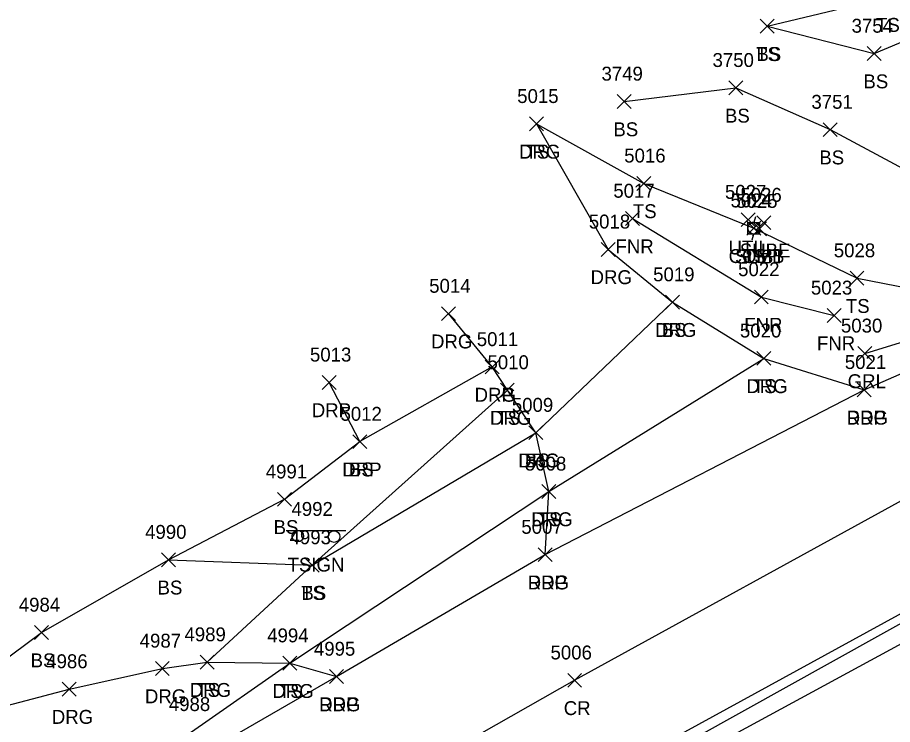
# Model space of a CAD drawing. Extents: x 1505656 to 1508446, y 700805 to 703031.
# Drawn here: x 1506226.3 to 1506352.2, y 701708.7 to 701810.4 of the extents above; entities that cross this region are included whole.
import ezdxf

# ---------------------------------------------------------------- set-up
doc = ezdxf.new("R2010")
doc.units = 0
for name, color, linetype in [('L_A', 7, 'Continuous'), ('L_I', 7, 'Continuous'), ('L_TIC', 7, 'Continuous'), ('LASF', 7, 'Continuous'), ('LELB', 7, 'Continuous'), ('LFNC', 7, 'Continuous'), ('P_A', 7, 'Continuous'), ('P_I', 7, 'Continuous'), ('P_TIC', 7, 'Continuous'), ('PET', 7, 'Continuous'), ('PRC', 7, 'Continuous'), ('R_A', 7, 'Continuous'), ('R_I', 7, 'Continuous'), ('R_TIC', 7, 'Continuous'), ('RDG', 7, 'Continuous'), ('RDP', 7, 'Continuous'), ('RGR', 7, 'Continuous'), ('S_A', 7, 'Continuous'), ('S_I', 7, 'Continuous'), ('SSGN', 7, 'Continuous'), ('U_A', 7, 'Continuous'), ('U_I', 7, 'Continuous'), ('U_TIC', 7, 'Continuous'), ('UDEFAULT', 7, 'Continuous'), ('UP', 7, 'Continuous')]:
    doc.layers.add(name, color=color, linetype=linetype)

msp = doc.modelspace()

# ---------------------------------------------------------------- linework, layer by layer
at = {"layer": 'L_TIC'}
for points in [[(1506333.15, 701808.13), (1506335.15, 701810.13)], [(1506335.15, 701808.13), (1506333.15, 701810.13)], [(1506333.15, 701808.13), (1506335.15, 701810.13)], [(1506335.15, 701808.13), (1506333.15, 701810.13)], [(1506348.54, 701804.2), (1506350.54, 701806.2)], [(1506350.54, 701804.2), (1506348.54, 701806.2)], [(1506328.63, 701799.27), (1506330.63, 701801.27)], [(1506330.63, 701799.27), (1506328.63, 701801.27)], [(1506312.58, 701797.31), (1506314.58, 701799.31)], [(1506314.58, 701797.31), (1506312.58, 701799.31)], [(1506299.96, 701794.09), (1506301.96, 701796.09)], [(1506301.96, 701794.09), (1506299.96, 701796.09)], [(1506342.19, 701793.26), (1506344.19, 701795.26)], [(1506344.19, 701793.26), (1506342.19, 701795.26)], [(1506315.41, 701785.53), (1506317.41, 701787.53)], [(1506317.41, 701785.53), (1506315.41, 701787.53)], [(1506313.78, 701780.47), (1506315.78, 701782.47)], [(1506315.78, 701780.47), (1506313.78, 701782.47)], [(1506331.21, 701779.08), (1506333.21, 701781.08)], [(1506333.21, 701779.08), (1506331.21, 701781.08)], [(1506346.06, 701771.9), (1506348.06, 701773.9)], [(1506348.06, 701771.9), (1506346.06, 701773.9)], [(1506319.52, 701768.45), (1506321.52, 701770.45)], [(1506321.52, 701768.45), (1506319.52, 701770.45)], [(1506332.3, 701769.19), (1506334.3, 701771.19)], [(1506334.3, 701769.19), (1506332.3, 701771.19)], [(1506342.77, 701766.54), (1506344.77, 701768.54)], [(1506344.77, 701766.54), (1506342.77, 701768.54)], [(1506332.65, 701760.37), (1506334.65, 701762.37)], [(1506334.65, 701760.37), (1506332.65, 701762.37)], [(1506295.77, 701755.81), (1506297.77, 701757.81)], [(1506297.77, 701755.81), (1506295.77, 701757.81)], [(1506299.85, 701749.68), (1506301.85, 701751.68)], [(1506301.85, 701749.68), (1506299.85, 701751.68)], [(1506274.54, 701748.39), (1506276.54, 701750.39)], [(1506276.54, 701748.39), (1506274.54, 701750.39)], [(1506301.72, 701741.23), (1506303.72, 701743.23)], [(1506303.72, 701741.23), (1506301.72, 701743.23)], [(1506263.71, 701740.1), (1506265.71, 701742.1)], [(1506265.71, 701740.1), (1506263.71, 701742.1)], [(1506247.02, 701731.41), (1506249.02, 701733.41)], [(1506249.02, 701731.41), (1506247.02, 701733.41)], [(1506247.02, 701731.41), (1506249.02, 701733.41)], [(1506249.02, 701731.41), (1506247.02, 701733.41)], [(1506267.71, 701730.64), (1506269.71, 701732.64)], [(1506269.71, 701730.64), (1506267.71, 701732.64)], [(1506267.71, 701730.64), (1506269.71, 701732.64)], [(1506269.71, 701730.64), (1506267.71, 701732.64)], [(1506228.76, 701720.94), (1506230.76, 701722.94)], [(1506230.76, 701720.94), (1506228.76, 701722.94)], [(1506252.6, 701716.68), (1506254.6, 701718.68)], [(1506254.6, 701716.68), (1506252.6, 701718.68)], [(1506264.49, 701716.53), (1506266.49, 701718.53)], [(1506266.49, 701716.53), (1506264.49, 701718.53)]]:
    msp.add_lwpolyline(points, dxfattribs=at)
at = {"layer": 'LASF'}
msp.add_lwpolyline([(1506429.68, 701752.83), (1506443.79, 701749.58), (1506462.7, 701738.25), (1506448, 701734.79), (1506439.12, 701730.66), (1506414.7, 701723.7), (1506383.01, 701711.36), (1506356.51, 701697.3), (1506322.23, 701673.42), (1506294.03, 701680.48), (1506288.73, 701684.49), (1506312.05, 701697.87), (1506364.79, 701726.48), (1506396.56, 701742.51), (1506417.45, 701749.86)], dxfattribs=at)
at = {"layer": 'LELB'}
for points in [[(1506334.15, 701809.13), (1506349.54, 701805.2), (1506366.68, 701812.39), (1506381.99, 701819.88), (1506387.6, 701843.4)], [(1506334.15, 701809.13), (1506351.39, 701813.32), (1506364.07, 701815.2), (1506375.49, 701824.29), (1506380.43, 701837.23)], [(1506313.58, 701798.31), (1506329.63, 701800.27), (1506343.19, 701794.26), (1506361, 701784.72), (1506379.68, 701792.88), (1506403.16, 701804.05), (1506415.96, 701807.45), (1506430.34, 701803.3), (1506438.86, 701796.52), (1506455.96, 701772), (1506464.53, 701767.06), (1506468.29, 701757.43), (1506462.7, 701738.25), (1506453.06, 701729.73), (1506439.12, 701730.66)], [(1506300.96, 701795.09), (1506316.41, 701786.53), (1506332.21, 701780.08), (1506347.06, 701772.9), (1506358.64, 701770.66), (1506379.38, 701774.98), (1506399.48, 701783.43), (1506418.59, 701789.11)], [(1506184.83, 701679.05), (1506205.21, 701698.56), (1506210.57, 701707.7), (1506229.76, 701721.94), (1506248.02, 701732.41), (1506268.71, 701731.64), (1506300.85, 701750.68), (1506320.52, 701769.45)], [(1506172.04, 701663.28), (1506192.25, 701675.22), (1506214.19, 701688.79), (1506251.34, 701707.65), (1506265.49, 701717.53), (1506302.72, 701742.23), (1506333.65, 701761.37)], [(1506253.6, 701717.68), (1506268.71, 701731.64), (1506296.77, 701756.81)], [(1506248.02, 701732.41), (1506264.71, 701741.1), (1506275.54, 701749.39)]]:
    msp.add_lwpolyline(points, dxfattribs=at)
at = {"layer": 'LFNC'}
msp.add_lwpolyline([(1506314.78, 701781.47), (1506333.3, 701770.19), (1506343.77, 701767.54)], dxfattribs=at)
at = {"layer": 'P_TIC'}
for points in [[(1506347.09, 701755.84), (1506349.09, 701757.84)], [(1506349.09, 701755.84), (1506347.09, 701757.84)], [(1506301.2, 701732.14), (1506303.2, 701734.14)], [(1506303.2, 701732.14), (1506301.2, 701734.14)], [(1506271.21, 701714.61), (1506273.21, 701716.61)], [(1506273.21, 701714.61), (1506271.21, 701716.61)], [(1506305.45, 701714.07), (1506307.45, 701716.07)], [(1506307.45, 701714.07), (1506305.45, 701716.07)]]:
    msp.add_lwpolyline(points, dxfattribs=at)
at = {"layer": 'PET'}
for points in [[(1505981.01, 701553.68), (1506020.04, 701573.54), (1506047.43, 701586.84), (1506064.36, 701596.59), (1506091.54, 701613.44), (1506142.35, 701641.39), (1506170.77, 701656.92), (1506194.97, 701672.06), (1506198.42, 701673.57), (1506217.27, 701683.91), (1506272.21, 701715.61), (1506302.2, 701733.14), (1506348.09, 701756.84), (1506381.24, 701771.36), (1506401.82, 701779.86), (1506418.98, 701787.96), (1506419.65, 701788)], [(1505992.82, 701526.62), (1506019.68, 701536.96), (1506041.12, 701547.38), (1506078.94, 701568.61), (1506107.14, 701585.72), (1506155.42, 701613.4), (1506197.61, 701637.13), (1506235.98, 701659.24), (1506270.79, 701679.06), (1506309.7, 701700.77), (1506363.1, 701730.01), (1506394.98, 701746.14), (1506415.62, 701755.89), (1506435.04, 701763.8), (1506427.31, 701775.57), (1506419.65, 701788)]]:
    msp.add_lwpolyline(points, dxfattribs=at)
at = {"layer": 'PRC'}
msp.add_lwpolyline([(1505987, 701541.07), (1506027.82, 701560.7), (1506054.36, 701574.52), (1506099.99, 701598.76), (1506149.98, 701626.58), (1506191.41, 701650.15), (1506228.11, 701670.57), (1506265.76, 701691.98), (1506306.45, 701715.07), (1506355.45, 701742.05), (1506388.92, 701758.93), (1506408.16, 701767.63), (1506427.31, 701775.57)], dxfattribs=at)
at = {"layer": 'R_TIC'}
for points in [[(1506299.96, 701794.09), (1506301.96, 701796.09)], [(1506301.96, 701794.09), (1506299.96, 701796.09)], [(1506310.26, 701776.04), (1506312.26, 701778.04)], [(1506312.26, 701776.04), (1506310.26, 701778.04)], [(1506319.52, 701768.45), (1506321.52, 701770.45)], [(1506321.52, 701768.45), (1506319.52, 701770.45)], [(1506287.3, 701766.8), (1506289.3, 701768.8)], [(1506289.3, 701766.8), (1506287.3, 701768.8)], [(1506347.17, 701761.08), (1506349.17, 701763.08)], [(1506349.17, 701761.08), (1506347.17, 701763.08)], [(1506332.65, 701760.37), (1506334.65, 701762.37)], [(1506334.65, 701760.37), (1506332.65, 701762.37)], [(1506293.57, 701759.13), (1506295.57, 701761.13)], [(1506295.57, 701759.13), (1506293.57, 701761.13)], [(1506293.57, 701759.13), (1506295.57, 701761.13)], [(1506295.57, 701759.13), (1506293.57, 701761.13)], [(1506270.15, 701756.91), (1506272.15, 701758.91)], [(1506272.15, 701756.91), (1506270.15, 701758.91)], [(1506295.77, 701755.81), (1506297.77, 701757.81)], [(1506297.77, 701755.81), (1506295.77, 701757.81)], [(1506347.09, 701755.84), (1506349.09, 701757.84)], [(1506349.09, 701755.84), (1506347.09, 701757.84)], [(1506299.85, 701749.68), (1506301.85, 701751.68)], [(1506301.85, 701749.68), (1506299.85, 701751.68)], [(1506274.54, 701748.39), (1506276.54, 701750.39)], [(1506276.54, 701748.39), (1506274.54, 701750.39)], [(1506301.72, 701741.23), (1506303.72, 701743.23)], [(1506303.72, 701741.23), (1506301.72, 701743.23)], [(1506301.2, 701732.14), (1506303.2, 701734.14)], [(1506303.2, 701732.14), (1506301.2, 701734.14)], [(1506252.6, 701716.68), (1506254.6, 701718.68)], [(1506254.6, 701716.68), (1506252.6, 701718.68)], [(1506264.49, 701716.53), (1506266.49, 701718.53)], [(1506266.49, 701716.53), (1506264.49, 701718.53)], [(1506246.15, 701715.77), (1506248.15, 701717.77)], [(1506248.15, 701715.77), (1506246.15, 701717.77)], [(1506271.21, 701714.61), (1506273.21, 701716.61)], [(1506273.21, 701714.61), (1506271.21, 701716.61)], [(1506232.76, 701712.81), (1506234.76, 701714.81)], [(1506234.76, 701712.81), (1506232.76, 701714.81)]]:
    msp.add_lwpolyline(points, dxfattribs=at)
at = {"layer": 'RDG'}
for points in [[(1506300.96, 701795.09), (1506311.26, 701777.04), (1506320.52, 701769.45), (1506333.65, 701761.37), (1506348.09, 701756.84)], [(1506302.2, 701733.14), (1506302.72, 701742.23), (1506300.85, 701750.68), (1506296.77, 701756.81), (1506294.57, 701760.13), (1506288.3, 701767.8)], [(1506199.34, 701711.36), (1506210.57, 701707.7), (1506233.76, 701713.81), (1506247.15, 701716.77), (1506253.6, 701717.68), (1506265.49, 701717.53), (1506272.21, 701715.61)]]:
    msp.add_lwpolyline(points, dxfattribs=at)
at = {"layer": 'RDP'}
msp.add_lwpolyline([(1506294.57, 701760.13), (1506275.54, 701749.39), (1506271.15, 701757.91)], dxfattribs=at)
at = {"layer": 'RGR'}
for points in [[(1506348.17, 701762.08), (1506380.89, 701772.12), (1506400.77, 701781.19), (1506418.59, 701789.11)], [(1506085.73, 701568.29), (1506107.54, 701584.72), (1506155.8, 701612.35), (1506198.2, 701636.56), (1506236.66, 701658.36), (1506270.99, 701677.92), (1506310.51, 701699.4), (1506363.66, 701728.98), (1506395.74, 701744.99), (1506415.68, 701754.26), (1506427.01, 701758.86)]]:
    msp.add_lwpolyline(points, dxfattribs=at)
at = {"layer": 'SSGN'}
for p, q in [((1506264.97, 701736.63), (1506273.56, 701736.63)), ((1506268.99, 701735.73), (1506268.99, 701735.73))]:
    msp.add_line(p, q, dxfattribs=at)
for centre in [(1506266.63, 701735.8), (1506271.84, 701735.73)]:
    msp.add_circle(centre, 0.833, dxfattribs=at)
at = {"layer": 'U_TIC'}
for points in [[(1506332.67, 701779.88), (1506334.67, 701781.88)], [(1506334.67, 701779.88), (1506332.67, 701781.88)], [(1506332.02, 701779.01), (1506334.02, 701781.01)], [(1506334.02, 701779.01), (1506332.02, 701781.01)]]:
    msp.add_lwpolyline(points, dxfattribs=at)
at = {"layer": 'UDEFAULT'}
for points in [[(1506330.41, 701780.31), (1506332.41, 701782.31)], [(1506332.41, 701780.31), (1506330.41, 701782.31)]]:
    msp.add_lwpolyline(points, dxfattribs=at)
at = {"layer": 'UP'}
for p, q in [((1506332.46, 701781.74), (1506332.21, 701780.91)), ((1506331.37, 701779.24), (1506331.37, 701780.91)), ((1506331.37, 701780.91), (1506333.04, 701780.91)), ((1506332.21, 701780.08), (1506332.21, 701780.08)), ((1506333.04, 701780.91), (1506333.04, 701779.24)), ((1506333.04, 701779.24), (1506331.37, 701779.24)), ((1506331.96, 701778.41), (1506332.21, 701779.24))]:
    msp.add_line(p, q, dxfattribs=at)
msp.add_circle((1506332.21, 701780.08), 0.833, dxfattribs=at)

# ---------------------------------------------------------------- texts
at = {"layer": 'L_A'}
for s, p in [('TS', (1506349.8, 701808.32)), ('TS', (1506332.56, 701804.13)), ('BS', (1506332.59, 701804.13)), ('BS', (1506347.98, 701800.2)), ('BS', (1506328.07, 701795.27)), ('BS', (1506312.02, 701793.31)), ('TS', (1506299.37, 701790.09)), ('BS', (1506341.64, 701789.26)), ('TS', (1506314.82, 701781.53)), ('FNR', (1506312.32, 701776.47)), ('TS', (1506330.62, 701775.08)), ('TS', (1506345.46, 701767.9)), ('BS', (1506318.96, 701764.45)), ('FNR', (1506330.84, 701765.19)), ('FNR', (1506341.3, 701762.54)), ('TS', (1506332.06, 701756.37)), ('TS', (1506295.18, 701751.81)), ('BS', (1506299.29, 701745.68)), ('BS', (1506273.98, 701744.39)), ('TS', (1506301.13, 701737.23)), ('BS', (1506263.15, 701736.1)), ('BS', (1506246.46, 701727.41)), ('BS', (1506246.46, 701727.41)), ('TS', (1506267.12, 701726.64)), ('BS', (1506267.15, 701726.64)), ('BS', (1506228.2, 701716.94)), ('TS', (1506252.01, 701712.68)), ('TS', (1506263.9, 701712.53))]:
    msp.add_text(s, height=2, dxfattribs=at).set_placement(p)
at = {"layer": 'L_I'}
for s, p in [('3754', (1506346.28, 701808.2)), ('3750', (1506326.28, 701803.27)), ('3749', (1506310.31, 701801.31)), ('5015', (1506298.19, 701798.09)), ('3751', (1506340.5, 701797.26)), ('5016', (1506313.58, 701789.53)), ('5017', (1506312.01, 701784.47)), ('5024', (1506328.87, 701783.08)), ('5028', (1506343.72, 701775.9)), ('5022', (1506329.96, 701773.19)), ('5019', (1506317.74, 701772.45)), ('5023', (1506340.43, 701770.54)), ('5020', (1506330.22, 701764.37)), ('5010', (1506293.91, 701759.81)), ('5009', (1506297.42, 701753.68)), ('5012', (1506272.77, 701752.39)), ('4991', (1506262.02, 701744.1)), ('5008', (1506299.3, 701745.23)), ('4990', (1506244.67, 701735.41)), ('4990', (1506244.67, 701735.41)), ('4993', (1506265.45, 701734.64)), ('4993', (1506265.45, 701734.64)), ('4984', (1506226.5, 701724.94)), ('4989', (1506250.33, 701720.68)), ('4994', (1506262.23, 701720.53)), ('4988', (1506248.08, 701710.65))]:
    msp.add_text(s, height=2, dxfattribs=at).set_placement(p)
at = {"layer": 'P_A'}
for s, p in [('RDP', (1506345.57, 701751.84)), ('RDP', (1506299.69, 701728.14)), ('RDP', (1506269.7, 701710.61)), ('CR', (1506304.88, 701710.07))]:
    msp.add_text(s, height=2, dxfattribs=at).set_placement(p)
at = {"layer": 'P_I'}
for s, p in [('5021', (1506345.31, 701759.84)), ('5007', (1506298.78, 701736.14)), ('4995', (1506268.95, 701718.61)), ('5006', (1506302.98, 701718.07))]:
    msp.add_text(s, height=2, dxfattribs=at).set_placement(p)
at = {"layer": 'R_A'}
for s, p in [('DRG', (1506298.45, 701790.09)), ('DRG', (1506308.74, 701772.04)), ('DRG', (1506318.01, 701764.45)), ('DRG', (1506285.79, 701762.8)), ('GRL', (1506345.72, 701757.08)), ('DRG', (1506331.14, 701756.37)), ('DRG', (1506292.06, 701755.13)), ('DRP', (1506292.06, 701755.13)), ('DRP', (1506268.64, 701752.91)), ('DRG', (1506294.26, 701751.81)), ('DRG', (1506345.57, 701751.84)), ('DRG', (1506298.34, 701745.68)), ('DRP', (1506273.03, 701744.39)), ('DRG', (1506300.21, 701737.23)), ('DRG', (1506299.69, 701728.14)), ('DRG', (1506251.09, 701712.68)), ('DRG', (1506244.64, 701711.77)), ('DRG', (1506262.98, 701712.53)), ('DRG', (1506269.7, 701710.61)), ('DRG', (1506231.25, 701708.81))]:
    msp.add_text(s, height=2, dxfattribs=at).set_placement(p)
at = {"layer": 'R_I'}
for s, p in [('5015', (1506298.19, 701798.09)), ('5018', (1506308.48, 701780.04)), ('5019', (1506317.74, 701772.45)), ('5014', (1506285.53, 701770.8)), ('5020', (1506330.22, 701764.37)), ('5030', (1506344.75, 701765.08)), ('5011', (1506292.37, 701763.13)), ('5011', (1506292.37, 701763.13)), ('5013', (1506268.38, 701760.91)), ('5010', (1506293.91, 701759.81)), ('5021', (1506345.31, 701759.84)), ('5009', (1506297.42, 701753.68)), ('5012', (1506272.77, 701752.39)), ('5008', (1506299.3, 701745.23)), ('5007', (1506298.78, 701736.14)), ('4989', (1506250.33, 701720.68)), ('4994', (1506262.23, 701720.53)), ('4987', (1506243.89, 701719.77)), ('4995', (1506268.95, 701718.61)), ('4986', (1506230.45, 701716.81))]:
    msp.add_text(s, height=2, dxfattribs=at).set_placement(p)
at = {"layer": 'S_A'}
msp.add_text('TSIGN', height=2, dxfattribs=at).set_placement((1506265.16, 701730.71))
at = {"layer": 'S_I'}
msp.add_text('4992', height=2, dxfattribs=at).set_placement((1506265.72, 701738.71))
at = {"layer": 'U_A'}
for s, p in [('UTIL', (1506328.58, 701776.31)), ('SUBE', (1506330.2, 701775.88)), ('COMB', (1506328.59, 701775.08)), ('SUBT', (1506329.52, 701775.01))]:
    msp.add_text(s, height=2, dxfattribs=at).set_placement(p)
at = {"layer": 'U_I'}
for s, p in [('5027', (1506328.07, 701784.31)), ('5024', (1506328.87, 701783.08)), ('5026', (1506330.28, 701783.88)), ('5025', (1506329.68, 701783.01))]:
    msp.add_text(s, height=2, dxfattribs=at).set_placement(p)

doc.saveas('drawing.dxf')
